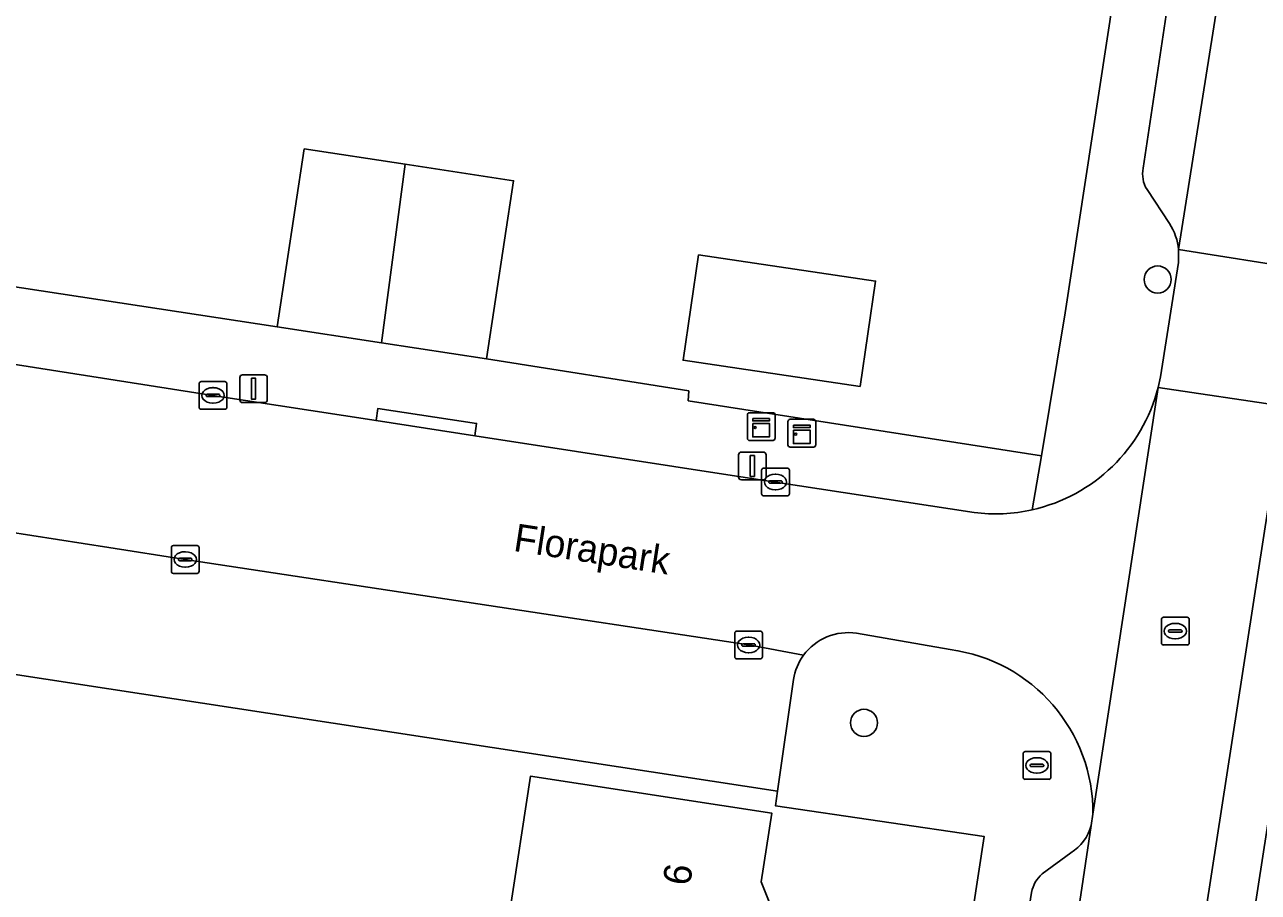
# Model space of a CAD drawing. Extents: x 161483 to 162250, y 379484 to 380833.
# Drawn here: x 161996.97 to 162041.42, y 380714.6 to 380745.87 of the extents above; entities that cross this region are included whole.
import ezdxf

# ---------------------------------------------------------------- set-up
doc = ezdxf.new("R2010")
doc.units = 0
for name, color, linetype in [('IMGEO_Boom', 7, 'Continuous'), ('IMGEO_Brandkraan', 7, 'Continuous'), ('IMGEO_Erf', 7, 'Continuous'), ('IMGEO_Kast', 7, 'Continuous'), ('IMGEO_Kolk', 7, 'Continuous'), ('IMGEO_Lichtmast', 7, 'Continuous'), ('IMGEO_Muur', 7, 'Continuous'), ('IMGEO_Openbare_ruimte_label', 7, 'Continuous'), ('IMGEO_Pand', 7, 'Continuous'), ('IMGEO_Pand_nummerreeks', 7, 'Continuous'), ('IMGEO_Parkeervlak_open', 7, 'Continuous'), ('IMGEO_Rijbaan_lokaal_open', 7, 'Continuous'), ('IMGEO_Rioolput', 7, 'Continuous'), ('IMGEO_Voetpad_open', 7, 'Continuous')]:
    doc.layers.add(name, color=color, linetype=linetype)

msp = doc.modelspace()

# ---------------------------------------------------------------- linework, layer by layer
at = {"layer": 'IMGEO_Boom'}
for centre in [(162037.797, 380736.686), (162027.214, 380720.706)]:
    msp.add_circle(centre, 0.489, dxfattribs=at)
at = {"layer": 'IMGEO_Brandkraan'}
for p, q in [((162033.021, 380719.671), (162033.873, 380719.671)), ((162032.946, 380718.745), (162032.946, 380719.597)), ((162033.248, 380719.214), (162033.646, 380719.214)), ((162033.434, 380719.451), (162033.459, 380719.451)), ((162033.947, 380719.597), (162033.947, 380718.745)), ((162033.205, 380719.165), (162033.205, 380719.177)), ((162033.643, 380719.128), (162033.245, 380719.128)), ((162033.457, 380718.891), (162033.432, 380718.891)), ((162033.689, 380719.177), (162033.689, 380719.165)), ((162033.873, 380718.671), (162033.021, 380718.671))]:
    msp.add_line(p, q, dxfattribs=at)
for points in [[(162033.021, 380719.671), (162033.873, 380719.671)], [(162032.946, 380718.745), (162032.946, 380719.597)], [(162033.947, 380719.597), (162033.947, 380718.745)], [(162033.873, 380718.671), (162033.021, 380718.671)]]:
    msp.add_lwpolyline(points, dxfattribs=at)
for centre, radius, start, end in [((162033.023, 380719.595), 0.0765, 91.552, 178.448), ((162033.023, 380719.595), 0.0765, 91.552, 178.448), ((162033.871, 380719.595), 0.0765, 1.552, 88.448), ((162033.871, 380719.595), 0.0765, 1.552, 88.448), ((162033.245, 380719.174), 0.0403, 85.8775, 175.7526), ((162033.65, 380719.176), 0.0386, 1.7309, 96.639), ((162033.242, 380719.164), 0.0366, 178.938, 274.7102), ((162033.646, 380719.171), 0.043, 264.8664, 352.4533), ((162033.023, 380718.747), 0.0765, 181.552, 268.448), ((162033.023, 380718.747), 0.0765, 181.552, 268.448), ((162033.871, 380718.747), 0.0765, 271.552, 358.448), ((162033.871, 380718.747), 0.0765, 271.552, 358.448)]:
    msp.add_arc(centre, radius, start, end, dxfattribs=at)
for centre, major_axis, ratio, start_param, end_param in [((162033.433, 380719.171), (-0.387, 0.002), 0.722429, 4.712389, 7.853982), ((162033.458, 380719.171), (-0.39, 0.002), 0.717154, 1.570796, 4.712389)]:
    msp.add_ellipse(centre, major_axis=major_axis, ratio=ratio, start_param=start_param, end_param=end_param, dxfattribs=at)
at = {"layer": 'IMGEO_Erf'}
for points in [[(161968.855, 380746.865), (161968.233, 380742.782), (161970.21, 380742.48), (161969.907, 380740.493), (161983.164, 380738.471), (161984.094, 380744.572), (161988.554, 380743.892), (161988.91, 380743.838), (161988.952, 380744.114), (161992.856, 380743.519), (161991.884, 380737.142), (162006.07, 380734.98), (162007.048, 380741.396), (162010.684, 380740.841), (162014.59, 380740.245), (162013.612, 380733.829), (162020.903, 380732.668), (162020.884, 380732.317), (162033.612, 380730.332), (162034.458, 380735.482), (162036.685, 380750)], [(162020.445, 380644.581), (162030.496, 380709.789), (162031.542, 380716.615), (162024.026, 380717.715), (162024.102, 380718.247), (162000, 380721.938), (161993.02, 380723.007), (161992.867, 380723.03), (161992.821, 380722.728), (161984.494, 380724.06), (161985.301, 380729.182), (161981.521, 380729.764), (161968.659, 380731.745), (161957.44, 380733.472)], [(162014.437, 380713.839), (162015.196, 380718.781), (162023.894, 380717.449), (162023.515, 380714.978), (162023.865, 380714.079)]]:
    msp.add_lwpolyline(points, dxfattribs=at)
msp.add_lwpolyline([(162021.256, 380737.575), (162027.634, 380736.63), (162027.072, 380732.83), (162020.694, 380733.774)], close=True, dxfattribs=at)
at = {"layer": 'IMGEO_Kast'}
for p, q in [((162023.011, 380730.96), (162023.011, 380731.801)), ((162023.011, 380731.801), (162023.011, 380730.96)), ((162023.086, 380731.885), (162023.927, 380731.885)), ((162023.927, 380731.885), (162023.086, 380731.885)), ((162024.011, 380731.81), (162024.011, 380730.969)), ((162024.011, 380730.969), (162024.011, 380731.81)), ((162024.549, 380731.647), (162025.39, 380731.647)), ((162025.39, 380731.647), (162024.549, 380731.647)), ((162024.474, 380730.722), (162024.474, 380731.563)), ((162024.474, 380731.563), (162024.474, 380730.722)), ((162025.474, 380731.572), (162025.474, 380730.731)), ((162025.474, 380730.731), (162025.474, 380731.572)), ((162023.936, 380730.885), (162023.095, 380730.885)), ((162023.095, 380730.885), (162023.936, 380730.885)), ((162025.399, 380730.647), (162024.558, 380730.647)), ((162024.558, 380730.647), (162025.399, 380730.647))]:
    msp.add_line(p, q, dxfattribs=at)
for points in [[(162023.206, 380731.675), (162023.806, 380731.675), (162023.806, 380731.59), (162023.206, 380731.59), (162023.206, 380731.675)], [(162023.206, 380731.5), (162023.806, 380731.5), (162023.806, 380731.011), (162023.206, 380731.011), (162023.206, 380731.5)], [(162024.669, 380731.437), (162025.269, 380731.437), (162025.269, 380731.352), (162024.669, 380731.352), (162024.669, 380731.437)], [(162024.669, 380731.262), (162025.269, 380731.262), (162025.269, 380730.773), (162024.669, 380730.773), (162024.669, 380731.262)]]:
    msp.add_lwpolyline(points, dxfattribs=at)
for centre in [(162023.29, 380731.349), (162024.753, 380731.111)]:
    msp.add_circle(centre, 0.0377, dxfattribs=at)
for centre, start, end in [((162023.089, 380731.807), 92.4484, 184.2845), ((162023.089, 380731.807), 92.4484, 184.2845), ((162023.933, 380731.807), 2.4484, 94.2845), ((162023.933, 380731.807), 2.4484, 94.2845), ((162024.552, 380731.569), 92.4484, 184.2845), ((162024.552, 380731.569), 92.4484, 184.2845), ((162025.396, 380731.569), 2.4484, 94.2845), ((162025.396, 380731.569), 2.4484, 94.2845), ((162023.089, 380730.963), 182.4484, 274.2845), ((162023.089, 380730.963), 182.4484, 274.2845), ((162023.933, 380730.963), 272.4484, 4.2845), ((162023.933, 380730.963), 272.4484, 4.2845), ((162024.552, 380730.725), 182.4484, 274.2845), ((162024.552, 380730.725), 182.4484, 274.2845), ((162025.396, 380730.725), 272.4484, 4.2845), ((162025.396, 380730.725), 272.4484, 4.2845)]:
    msp.add_arc(centre, 0.0779, start, end, dxfattribs=at)
at = {"layer": 'IMGEO_Kolk'}
for p, q in [((162003.332, 380733.008), (162004.184, 380733.008)), ((162003.257, 380732.082), (162003.257, 380732.934)), ((162003.559, 380732.551), (162003.957, 380732.551)), ((162003.745, 380732.788), (162003.77, 380732.788)), ((162004.258, 380732.934), (162004.258, 380732.082)), ((162003.516, 380732.502), (162003.516, 380732.514)), ((162003.954, 380732.465), (162003.556, 380732.465)), ((162003.768, 380732.228), (162003.743, 380732.228)), ((162004, 380732.514), (162004, 380732.502)), ((162004.184, 380732.008), (162003.332, 380732.008)), ((162023.599, 380729.888), (162024.451, 380729.888)), ((162023.524, 380728.962), (162023.524, 380729.814)), ((162023.826, 380729.431), (162024.224, 380729.431)), ((162024.012, 380729.668), (162024.037, 380729.668)), ((162024.525, 380729.814), (162024.525, 380728.962)), ((162023.783, 380729.382), (162023.783, 380729.394)), ((162024.221, 380729.345), (162023.823, 380729.345)), ((162024.035, 380729.108), (162024.01, 380729.108)), ((162024.267, 380729.394), (162024.267, 380729.382)), ((162024.451, 380728.888), (162023.599, 380728.888)), ((162002.257, 380726.169), (162002.257, 380727.021)), ((162002.332, 380727.095), (162003.184, 380727.095)), ((162002.745, 380726.875), (162002.77, 380726.875)), ((162003.258, 380727.021), (162003.258, 380726.169)), ((162002.516, 380726.589), (162002.516, 380726.601)), ((162002.954, 380726.552), (162002.556, 380726.552)), ((162002.559, 380726.638), (162002.957, 380726.638)), ((162002.768, 380726.315), (162002.743, 380726.315)), ((162003, 380726.601), (162003, 380726.589)), ((162003.184, 380726.095), (162002.332, 380726.095)), ((162022.556, 380723.088), (162022.556, 380723.94)), ((162022.631, 380724.014), (162023.483, 380724.014)), ((162023.044, 380723.794), (162023.069, 380723.794)), ((162023.557, 380723.94), (162023.557, 380723.088)), ((162022.815, 380723.508), (162022.815, 380723.52)), ((162023.253, 380723.471), (162022.855, 380723.471)), ((162022.858, 380723.557), (162023.256, 380723.557)), ((162023.067, 380723.234), (162023.042, 380723.234)), ((162023.299, 380723.52), (162023.299, 380723.508)), ((162023.483, 380723.014), (162022.631, 380723.014))]:
    msp.add_line(p, q, dxfattribs=at)
for points in [[(162003.332, 380733.008), (162004.184, 380733.008)], [(162003.257, 380732.082), (162003.257, 380732.934)], [(162004.258, 380732.934), (162004.258, 380732.082)], [(162004.184, 380732.008), (162003.332, 380732.008)], [(162023.599, 380729.888), (162024.451, 380729.888)], [(162023.524, 380728.962), (162023.524, 380729.814)], [(162024.525, 380729.814), (162024.525, 380728.962)], [(162024.451, 380728.888), (162023.599, 380728.888)], [(162002.257, 380726.169), (162002.257, 380727.021)], [(162002.332, 380727.095), (162003.184, 380727.095)], [(162003.258, 380727.021), (162003.258, 380726.169)], [(162003.184, 380726.095), (162002.332, 380726.095)], [(162022.556, 380723.088), (162022.556, 380723.94)], [(162022.631, 380724.014), (162023.483, 380724.014)], [(162023.557, 380723.94), (162023.557, 380723.088)], [(162023.483, 380723.014), (162022.631, 380723.014)]]:
    msp.add_lwpolyline(points, dxfattribs=at)
for centre, radius, start, end in [((162003.334, 380732.932), 0.0765, 91.552, 178.448), ((162003.334, 380732.932), 0.0765, 91.552, 178.448), ((162004.182, 380732.932), 0.0765, 1.552, 88.448), ((162004.182, 380732.932), 0.0765, 1.552, 88.448), ((162003.556, 380732.511), 0.0403, 85.8775, 175.7526), ((162003.961, 380732.513), 0.0386, 1.7309, 96.639), ((162003.553, 380732.501), 0.0366, 178.938, 274.7102), ((162003.957, 380732.508), 0.043, 264.8664, 352.4533), ((162003.334, 380732.084), 0.0765, 181.552, 268.448), ((162003.334, 380732.084), 0.0765, 181.552, 268.448), ((162004.182, 380732.084), 0.0765, 271.552, 358.448), ((162004.182, 380732.084), 0.0765, 271.552, 358.448), ((162023.601, 380729.812), 0.0765, 91.552, 178.448), ((162023.601, 380729.812), 0.0765, 91.552, 178.448), ((162024.449, 380729.812), 0.0765, 1.552, 88.448), ((162024.449, 380729.812), 0.0765, 1.552, 88.448), ((162023.823, 380729.391), 0.0403, 85.8775, 175.7526), ((162024.228, 380729.393), 0.0386, 1.7309, 96.639), ((162023.82, 380729.381), 0.0366, 178.938, 274.7102), ((162024.224, 380729.388), 0.043, 264.8664, 352.4533), ((162023.601, 380728.964), 0.0765, 181.552, 268.448), ((162023.601, 380728.964), 0.0765, 181.552, 268.448), ((162024.449, 380728.964), 0.0765, 271.552, 358.448), ((162024.449, 380728.964), 0.0765, 271.552, 358.448), ((162002.334, 380727.019), 0.0765, 91.552, 178.448), ((162002.334, 380727.019), 0.0765, 91.552, 178.448), ((162003.182, 380727.019), 0.0765, 1.552, 88.448), ((162003.182, 380727.019), 0.0765, 1.552, 88.448), ((162002.556, 380726.598), 0.0403, 85.8775, 175.7526), ((162002.553, 380726.588), 0.0366, 178.938, 274.7102), ((162002.957, 380726.595), 0.043, 264.8664, 352.4533), ((162002.961, 380726.6), 0.0386, 1.7309, 96.639), ((162002.334, 380726.171), 0.0765, 181.552, 268.448), ((162002.334, 380726.171), 0.0765, 181.552, 268.448), ((162003.182, 380726.171), 0.0765, 271.552, 358.448), ((162003.182, 380726.171), 0.0765, 271.552, 358.448), ((162022.633, 380723.938), 0.0765, 91.552, 178.448), ((162022.633, 380723.938), 0.0765, 91.552, 178.448), ((162023.481, 380723.938), 0.0765, 1.552, 88.448), ((162023.481, 380723.938), 0.0765, 1.552, 88.448), ((162022.855, 380723.517), 0.0403, 85.8775, 175.7526), ((162022.852, 380723.507), 0.0366, 178.938, 274.7102), ((162023.256, 380723.514), 0.043, 264.8664, 352.4533), ((162023.26, 380723.519), 0.0386, 1.7309, 96.639), ((162022.633, 380723.09), 0.0765, 181.552, 268.448), ((162022.633, 380723.09), 0.0765, 181.552, 268.448), ((162023.481, 380723.09), 0.0765, 271.552, 358.448), ((162023.481, 380723.09), 0.0765, 271.552, 358.448)]:
    msp.add_arc(centre, radius, start, end, dxfattribs=at)
for centre, major_axis, ratio, start_param, end_param in [((162003.744, 380732.508), (-0.387, 0.002), 0.722429, 4.712389, 7.853982), ((162003.769, 380732.508), (-0.39, 0.002), 0.717154, 1.570796, 4.712389), ((162024.011, 380729.388), (-0.387, 0.002), 0.722429, 4.712389, 7.853982), ((162024.036, 380729.388), (-0.39, 0.002), 0.717154, 1.570796, 4.712389), ((162002.744, 380726.595), (-0.387, 0.002), 0.722429, 4.712389, 7.853982), ((162002.769, 380726.595), (-0.39, 0.002), 0.717154, 1.570796, 4.712389), ((162023.043, 380723.514), (-0.387, 0.002), 0.722429, 4.712389, 7.853982), ((162023.068, 380723.514), (-0.39, 0.002), 0.717154, 1.570796, 4.712389)]:
    msp.add_ellipse(centre, major_axis=major_axis, ratio=ratio, start_param=start_param, end_param=end_param, dxfattribs=at)
at = {"layer": 'IMGEO_Lichtmast'}
for p, q in [((162004.724, 380732.35), (162004.724, 380733.15)), ((162004.724, 380733.15), (162004.724, 380732.35)), ((162004.824, 380733.25), (162005.614, 380733.25)), ((162005.614, 380733.25), (162004.824, 380733.25)), ((162005.714, 380733.15), (162005.714, 380732.35)), ((162005.714, 380732.35), (162005.714, 380733.15)), ((162005.614, 380732.25), (162004.824, 380732.25)), ((162004.824, 380732.25), (162005.614, 380732.25)), ((162022.696, 380729.566), (162022.696, 380730.366)), ((162022.696, 380730.366), (162022.696, 380729.566)), ((162022.796, 380730.466), (162023.586, 380730.466)), ((162023.586, 380730.466), (162022.796, 380730.466)), ((162023.686, 380730.366), (162023.686, 380729.566)), ((162023.686, 380729.566), (162023.686, 380730.366)), ((162023.586, 380729.466), (162022.796, 380729.466)), ((162022.796, 380729.466), (162023.586, 380729.466))]:
    msp.add_line(p, q, dxfattribs=at)
for points in [[(162005.144, 380733.125), (162005.294, 380733.125), (162005.294, 380732.375), (162005.144, 380732.375), (162005.144, 380733.125)], [(162023.116, 380730.341), (162023.266, 380730.341), (162023.266, 380729.591), (162023.116, 380729.591), (162023.116, 380730.341)]]:
    msp.add_lwpolyline(points, dxfattribs=at)
for centre, start, end in [((162004.824, 380733.15), 90, 180), ((162004.824, 380733.15), 90, 180), ((162005.614, 380733.15), 0, 90), ((162005.614, 380733.15), 360, 90), ((162004.824, 380732.35), 180, 270), ((162004.824, 380732.35), 180, 270), ((162005.614, 380732.35), 270, 0), ((162005.614, 380732.35), 270, 0), ((162022.796, 380730.366), 90, 180), ((162022.796, 380730.366), 90, 180), ((162023.586, 380730.366), 0, 90), ((162023.586, 380730.366), 360, 90), ((162022.796, 380729.566), 180, 270), ((162022.796, 380729.566), 180, 270), ((162023.586, 380729.566), 270, 0), ((162023.586, 380729.566), 270, 0)]:
    msp.add_arc(centre, 0.1, start, end, dxfattribs=at)
at = {"layer": 'IMGEO_Muur'}
msp.add_lwpolyline([(162006.07, 380734.98), (161991.884, 380737.142)], dxfattribs=at)
at = {"layer": 'IMGEO_Pand'}
for points in [[(162009.83, 380734.406), (162010.684, 380740.841), (162007.048, 380741.396), (162006.07, 380734.98)], [(162009.83, 380734.406), (162013.612, 380733.829), (162014.59, 380740.245), (162010.684, 380740.841)], [(162027.072, 380732.83), (162027.634, 380736.63), (162021.256, 380737.575), (162020.694, 380733.774)], [(162023.052, 380711.872), (162023.587, 380712.264), (162023.865, 380714.079), (162023.515, 380714.978), (162023.894, 380717.449), (162015.196, 380718.781), (162014.437, 380713.839), (162014.339, 380713.202)]]:
    msp.add_lwpolyline(points, close=True, dxfattribs=at)
at = {"layer": 'IMGEO_Parkeervlak_open'}
for points in [[(162038.552, 380737.764), (162040.179, 380748.077), (162040.476, 380750), (162043.026, 380766.873), (162043.54, 380770.256)], [(162041.36, 380767.565), (162038.678, 380750), (162038.324, 380747.678), (162037.279, 380740.7)], [(162037.413, 380739.93), (162038.221, 380738.7)], [(162042.342, 380732.122), (162030.992, 380658.688)], [(162040.094, 380710.68), (162040.755, 380710.541), (162043.682, 380729.488)], [(162025.035, 380723.141), (162023.053, 380723.515), (162002.754, 380726.596), (162000, 380727.025), (161993.514, 380728.036)], [(161993.624, 380727.014), (161993.02, 380723.007), (162000, 380721.938), (162024.102, 380718.247), (162024.675, 380722.269)], [(162024.132, 380643.875), (162024.239, 380644.567), (162034.086, 380708.223), (162035.405, 380717.007)], [(162034.67, 380716.023), (162033.637, 380715.265)], [(162033.254, 380714.598), (162032.206, 380707.971), (162030.147, 380694.5), (162030.722, 380694.411)]]:
    msp.add_lwpolyline(points, dxfattribs=at)
for centre, radius, start, end in [((162038.271, 380740.476), 1.017, 167.2715, 212.4726), ((162036.477, 380737.557), 2.086, 5.7061, 33.2444), ((162026.62, 380721.976), 1.967, 143.6944, 171.4396), ((162033.758, 380717.471), 1.711, 302.2089, 344.2752), ((162034.368, 380714.402), 1.131, 130.2498, 170.0202)]:
    msp.add_arc(centre, radius, start, end, dxfattribs=at)
at = {"layer": 'IMGEO_Rijbaan_lokaal_open'}
for points in [[(162043.584, 380770.542), (162043.54, 380770.256), (162043.026, 380766.873), (162040.476, 380750), (162040.179, 380748.077), (162038.552, 380737.764), (162043.095, 380737.044), (162045.01, 380750), (162047.527, 380766.233)], [(162031.18, 380728.288), (162024.021, 380729.387), (162013.189, 380731.055), (162009.631, 380731.602), (162003.754, 380732.507), (162000, 380733.095), (161991.346, 380734.451), (161987.613, 380734.977), (161984.458, 380735.473), (161967.812, 380738.019), (161964.1, 380738.605), (161962.617, 380738.853), (161958.821, 380739.397), (161957.472, 380739.634), (161956.237, 380739.82)], [(162035.466, 380717.413), (162037.468, 380730.523), (162037.814, 380732.79)], [(161993.514, 380728.036), (162000, 380727.025), (162002.754, 380726.596), (162023.053, 380723.515), (162025.035, 380723.141)], [(162026.949, 380723.937), (162030.322, 380723.348)]]:
    msp.add_lwpolyline(points, dxfattribs=at)
for points in [[(162043.095, 380737.044), (162038.552, 380737.764), (162038.548, 380737.302), (162037.9, 380733.176), (162037.814, 380732.79), (162042.342, 380732.122), (162042.333, 380732.316), (162042.325, 380732.508), (162042.94, 380736.566), (162043.014, 380736.794)], [(162042.342, 380732.122), (162037.814, 380732.79), (162037.468, 380730.523), (162035.466, 380717.413), (162035.405, 380717.007), (162034.086, 380708.223), (162024.239, 380644.567), (162028.775, 380643.851), (162030.621, 380656.254), (162030.651, 380656.454), (162030.992, 380658.688)]]:
    msp.add_lwpolyline(points, close=True, dxfattribs=at)
for centre, radius, start, end in [((162031.946, 380734.297), 6.058, 282.6975, 345.5977), ((162031.947, 380734.306), 6.067, 262.7332, 282.6702), ((162026.644, 380721.971), 1.989, 81.1766, 143.9865), ((162029.535, 380717.469), 5.931, 359.4568, 82.3757)]:
    msp.add_arc(centre, radius, start, end, dxfattribs=at)
at = {"layer": 'IMGEO_Rioolput'}
for p, q in [((162037.931, 380723.587), (162037.931, 380724.439)), ((162038.006, 380724.513), (162038.858, 380724.513)), ((162038.419, 380724.293), (162038.444, 380724.293)), ((162038.932, 380724.439), (162038.932, 380723.587)), ((162038.19, 380724.007), (162038.19, 380724.019)), ((162038.628, 380723.97), (162038.23, 380723.97)), ((162038.233, 380724.056), (162038.631, 380724.056)), ((162038.442, 380723.733), (162038.417, 380723.733)), ((162038.674, 380724.019), (162038.674, 380724.007)), ((162038.858, 380723.513), (162038.006, 380723.513))]:
    msp.add_line(p, q, dxfattribs=at)
for points in [[(162037.931, 380723.587), (162037.931, 380724.439)], [(162038.006, 380724.513), (162038.858, 380724.513)], [(162038.932, 380724.439), (162038.932, 380723.587)], [(162038.858, 380723.513), (162038.006, 380723.513)]]:
    msp.add_lwpolyline(points, dxfattribs=at)
for centre, radius, start, end in [((162038.008, 380724.437), 0.0765, 91.552, 178.448), ((162038.008, 380724.437), 0.0765, 91.552, 178.448), ((162038.856, 380724.437), 0.0765, 1.552, 88.448), ((162038.856, 380724.437), 0.0765, 1.552, 88.448), ((162038.23, 380724.016), 0.0403, 85.8775, 175.7526), ((162038.227, 380724.006), 0.0366, 178.938, 274.7102), ((162038.631, 380724.013), 0.043, 264.8664, 352.4533), ((162038.635, 380724.018), 0.0386, 1.7309, 96.639), ((162038.008, 380723.589), 0.0765, 181.552, 268.448), ((162038.008, 380723.589), 0.0765, 181.552, 268.448), ((162038.856, 380723.589), 0.0765, 271.552, 358.448), ((162038.856, 380723.589), 0.0765, 271.552, 358.448)]:
    msp.add_arc(centre, radius, start, end, dxfattribs=at)
for centre, major_axis, ratio, start_param, end_param in [((162038.418, 380724.013), (-0.387, 0.002), 0.722429, 4.712389, 7.853982), ((162038.443, 380724.013), (-0.39, 0.002), 0.717154, 1.570796, 4.712389)]:
    msp.add_ellipse(centre, major_axis=major_axis, ratio=ratio, start_param=start_param, end_param=end_param, dxfattribs=at)
at = {"layer": 'IMGEO_Voetpad_open'}
for points in [[(162039.668, 380769.454), (162036.685, 380750), (162034.458, 380735.482), (162033.612, 380730.332), (162033.278, 380728.387)], [(162037.279, 380740.7), (162038.324, 380747.678), (162038.678, 380750), (162041.36, 380767.565)], [(162033.278, 380728.387), (162033.612, 380730.332), (162020.884, 380732.317), (162020.903, 380732.668), (162013.612, 380733.829), (162009.83, 380734.406), (162006.07, 380734.98), (161991.884, 380737.142), (161987.708, 380737.778), (161983.164, 380738.471), (161969.907, 380740.493), (161958.651, 380742.21), (161955.926, 380742.626), (161955.778, 380742.035), (161945.932, 380743.53), (161945.58, 380741.467), (161943.256, 380741.795), (161938.583, 380711.252), (161937.319, 380702.795), (161927.438, 380638.646)], [(161955.18, 380739.963), (161955.26, 380740.486), (161962.69, 380739.328), (161962.617, 380738.853), (161964.1, 380738.605), (161964.177, 380739.098), (161967.889, 380738.512), (161967.812, 380738.019), (161984.458, 380735.473), (161987.613, 380734.977), (161987.682, 380735.472), (161991.415, 380734.946), (161991.346, 380734.451), (162000, 380733.095), (162003.754, 380732.507), (162009.631, 380731.602), (162009.698, 380732.042), (162013.257, 380731.499), (162013.189, 380731.055), (162024.021, 380729.387), (162031.18, 380728.288)], [(162038.221, 380738.7), (162037.413, 380739.93)], [(162038.548, 380737.302), (162038.552, 380737.764)], [(162037.814, 380732.79), (162037.9, 380733.176), (162038.548, 380737.302)], [(162043.682, 380729.488), (162040.755, 380710.541), (162040.094, 380710.68)], [(162030.322, 380723.348), (162026.949, 380723.937)], [(162024.675, 380722.269), (162024.102, 380718.247), (162024.026, 380717.715), (162031.542, 380716.615), (162030.496, 380709.789), (162020.445, 380644.581), (162019.94, 380641.308), (162008.935, 380569.909), (162008.76, 380568.777), (162004.779, 380542.949)], [(162035.405, 380717.007), (162035.466, 380717.413)], [(162033.637, 380715.265), (162034.67, 380716.023)], [(162030.722, 380694.411), (162030.147, 380694.5), (162032.206, 380707.971), (162033.254, 380714.598)]]:
    msp.add_lwpolyline(points, dxfattribs=at)
msp.add_lwpolyline([(162013.189, 380731.055), (162013.257, 380731.499), (162009.698, 380732.042), (162009.631, 380731.602)], close=True, dxfattribs=at)
for centre, radius, start, end in [((162038.271, 380740.476), 1.017, 167.2715, 212.4726), ((162036.477, 380737.557), 2.086, 5.7061, 33.2444), ((162031.946, 380734.297), 6.058, 282.6975, 345.5977), ((162031.947, 380734.306), 6.067, 262.7332, 282.6702), ((162026.644, 380721.971), 1.989, 81.1766, 143.9865), ((162029.535, 380717.469), 5.931, 359.4568, 82.3757), ((162026.62, 380721.976), 1.967, 143.6944, 171.4396), ((162033.758, 380717.471), 1.711, 302.2089, 344.2752), ((162034.368, 380714.402), 1.131, 130.2498, 170.0202)]:
    msp.add_arc(centre, radius, start, end, dxfattribs=at)

# ---------------------------------------------------------------- texts
at = {"layer": 'IMGEO_Openbare_ruimte_label'}
msp.add_text('Florapark', height=1, rotation=351.2538, dxfattribs=at).set_placement((162014.552, 380726.908))
at = {"layer": 'IMGEO_Pand_nummerreeks'}
msp.add_text('6', height=1, rotation=81.3321, dxfattribs=at).set_placement((162020.941, 380714.803))

doc.saveas('drawing.dxf')
